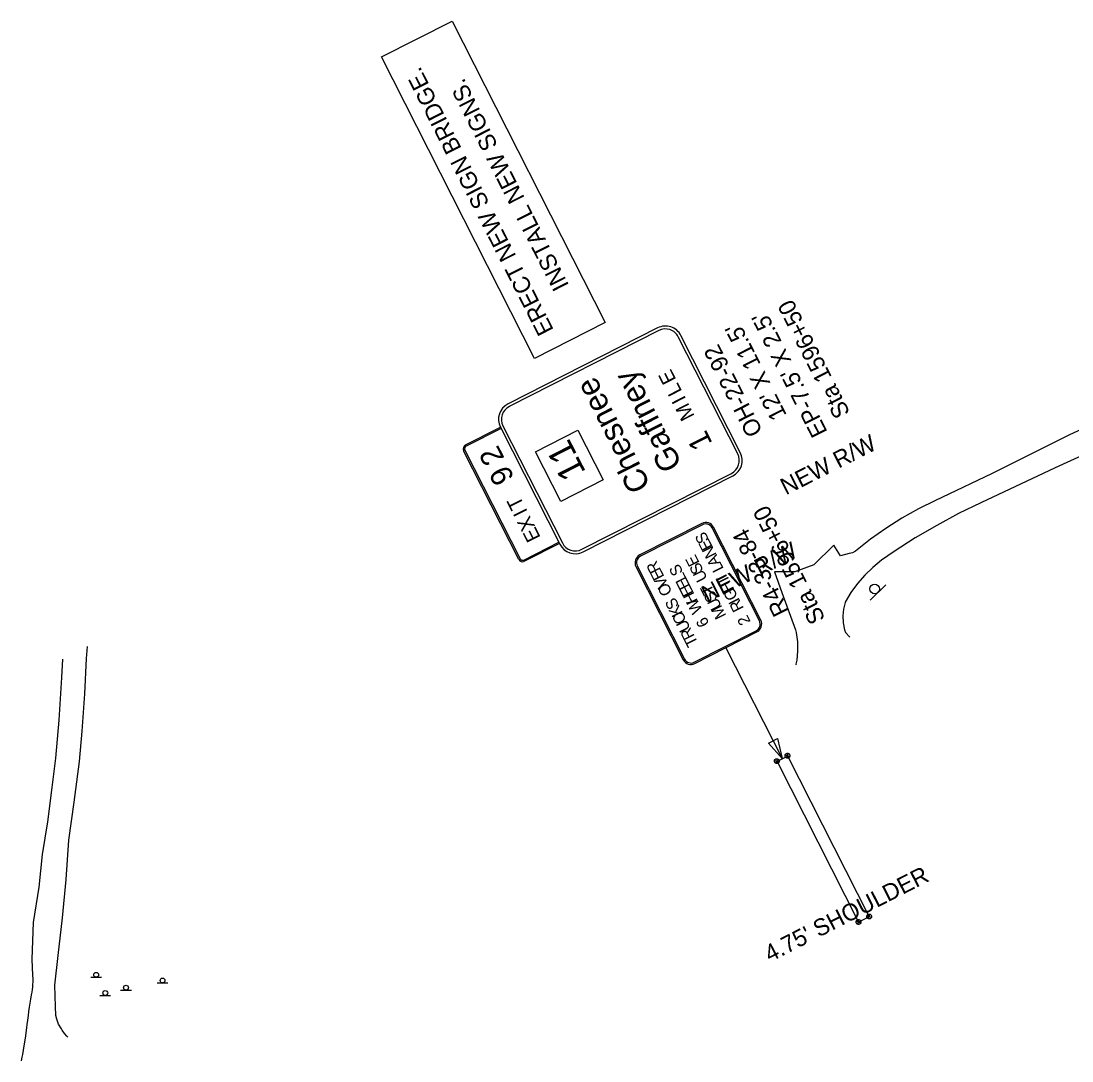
# Model space of a CAD drawing. Extents: x 1806030 to 1807588, y 1188872 to 1190302.
# Drawn here: x 1806373.9 to 1806808.9, y 1189423.6 to 1189854 of the extents above; entities that cross this region are included whole.
import ezdxf

# ---------------------------------------------------------------- set-up
doc = ezdxf.new("R2010")
doc.units = 0
for name, color, linetype in [('RD_EX_Road', 7, 'Continuous'), ('RD_PD_Final_TX', 7, 'Continuous'), ('RD_PD_RW_TX', 7, 'Continuous'), ('SN_P_Signs', 7, 'Continuous')]:
    doc.layers.add(name, color=color, linetype=linetype)

msp = doc.modelspace()

# ---------------------------------------------------------------- linework, layer by layer
at = {"layer": 'RD_EX_Road'}
for points in [[(1806841.36, 1189698.26), (1806807.68, 1189682.56), (1806775.95, 1189666.81), (1806755.12, 1189656.88), (1806752.39, 1189655.63), (1806745.38, 1189652.11), (1806738.55, 1189648.25), (1806731.93, 1189644.05), (1806725.53, 1189639.52), (1806719.36, 1189634.67), (1806718.02, 1189633.98), (1806716.66, 1189633.64), (1806713.08, 1189632.65), (1806710.3, 1189637.13), (1806702.13, 1189628.91), (1806694.17, 1189626.05), (1806685.79, 1189626), (1806688.83, 1189617.5), (1806694.53, 1189602.11), (1806694.77, 1189600.9), (1806695.26, 1189597.09), (1806695.35, 1189593.26), (1806695.04, 1189589.44), (1806694.61, 1189587.88), (1806694.72, 1189587.51)], [(1806832.14, 1189682.96), (1806802.05, 1189669.06), (1806771.24, 1189654.68), (1806762, 1189650.16), (1806752.93, 1189645.29), (1806744.06, 1189640.07), (1806735.4, 1189634.52), (1806730.02, 1189630.82), (1806726.46, 1189627.9), (1806723.16, 1189624.69), (1806720.15, 1189621.2), (1806717.45, 1189617.47), (1806715.08, 1189613.52), (1806715.02, 1189613.41), (1806714.38, 1189610.62), (1806714.13, 1189607.78), (1806714.27, 1189604.92), (1806714.8, 1189602.11), (1806715.16, 1189600.9), (1806716.93, 1189599.03)], [(1806393.31, 1189433.47), (1806392.88, 1189433.84), (1806391.85, 1189435), (1806390.97, 1189436.29), (1806390.6, 1189436.95), (1806389.45, 1189438.86), (1806388.65, 1189440.95), (1806388.32, 1189442.47), (1806388.09, 1189446.15), (1806387.87, 1189454.99), (1806389.31, 1189467.19), (1806390.99, 1189482.78), (1806392.5, 1189498.73), (1806393.69, 1189515), (1806395.82, 1189530.65), (1806398.14, 1189547.51), (1806399.23, 1189560.09), (1806400.26, 1189575.6), (1806401.04, 1189590.17), (1806401.38, 1189595.11)], [(1806390.99, 1189589.96), (1806390.57, 1189582.3), (1806389.55, 1189564.61), (1806388.18, 1189548.93), (1806386.64, 1189536.83), (1806384.83, 1189522.61), (1806382.57, 1189509.07), (1806381.25, 1189495.55), (1806378.83, 1189480.85), (1806378.35, 1189465.79), (1806378.66, 1189458.95), (1806378.77, 1189457.79), (1806378.81, 1189456.51), (1806378.69, 1189455.04), (1806378.61, 1189454.08), (1806378.48, 1189453.16), (1806378.3, 1189452.14), (1806378.06, 1189450.91), (1806377.76, 1189449.17), (1806377.19, 1189445.88), (1806376.94, 1189444.04), (1806376.76, 1189442.42), (1806376.51, 1189440.46), (1806376.34, 1189438.75), (1806376.09, 1189437.29), (1806375.57, 1189432.98), (1806375.03, 1189429.83), (1806374.7, 1189428), (1806374.42, 1189426.27), (1806374.22, 1189425.23), (1806373.87, 1189423.59)]]:
    msp.add_lwpolyline(points, dxfattribs=at)
at = {"layer": 'SN_P_Signs'}
for p, q in [((1806523.05, 1189839.18), (1806552.3, 1189854.04)), ((1806552.3, 1189854.04), (1806615.68, 1189729.26)), ((1806586.44, 1189714.41), (1806523.05, 1189839.18)), ((1806615.68, 1189729.26), (1806586.44, 1189714.41)), ((1806637.9, 1189725.94), (1806576.02, 1189694.51)), ((1806586.88, 1189675.77), (1806604.43, 1189684.69)), ((1806604.43, 1189684.69), (1806614.88, 1189664.12)), ((1806606.06, 1189635.38), (1806667.94, 1189666.82)), ((1806614.88, 1189664.12), (1806597.33, 1189655.2)), ((1806725.46, 1189614.36), (1806731.82, 1189620.72)), ((1806665.69, 1189594.63), (1806688.95, 1189548.84)), ((1806691.25, 1189549.78), (1806686.83, 1189547.53)), ((1806690.21, 1189550.28), (1806692.1, 1189549.66)), ((1806690.85, 1189549.02), (1806691.47, 1189550.91)), ((1806724.99, 1189483.36), (1806691.25, 1189549.78)), ((1806685.79, 1189548.03), (1806687.69, 1189547.41)), ((1806686.43, 1189546.77), (1806687.05, 1189548.67)), ((1806686.83, 1189547.53), (1806720.58, 1189481.11)), ((1806724.68, 1189482.41), (1806725.3, 1189484.3)), ((1806719.63, 1189481.42), (1806721.52, 1189480.8)), ((1806720.27, 1189480.16), (1806720.89, 1189482.06)), ((1806720.58, 1189481.11), (1806724.99, 1189483.36)), ((1806724.05, 1189483.67), (1806725.94, 1189483.05)), ((1806402.73, 1189458.27), (1806407.23, 1189458.27)), ((1806430.21, 1189455.89), (1806434.71, 1189455.89)), ((1806406.48, 1189450.72), (1806410.98, 1189450.72)), ((1806415.08, 1189452.91), (1806419.58, 1189452.91))]:
    msp.add_line(p, q, dxfattribs=at)
for points in [[(1806637.35, 1189727.01), (1806575.48, 1189695.58)], [(1806670.57, 1189674.88), (1806645.97, 1189723.31)], [(1806671.64, 1189675.43), (1806647.04, 1189723.85)], [(1806557.88, 1189678.56), (1806572.32, 1189685.9), (1806572.59, 1189685.36)], [(1806572.59, 1189685.36), (1806558.15, 1189678.03)], [(1806572.32, 1189685.9), (1806596.92, 1189637.47)], [(1806573.39, 1189686.44), (1806597.99, 1189638.01)], [(1806579.92, 1189631.21), (1806557.09, 1189676.14)], [(1806557.62, 1189676.41), (1806580.45, 1189631.48)], [(1806597.33, 1189655.2), (1806586.88, 1189675.77)], [(1806606.6, 1189634.31), (1806668.48, 1189665.75)], [(1806655.7, 1189646.08), (1806630.02, 1189633.04)], [(1806655.97, 1189645.55), (1806630.29, 1189632.5)], [(1806679.57, 1189605.72), (1806660, 1189644.23)], [(1806680.1, 1189605.99), (1806660.54, 1189644.5)], [(1806582.06, 1189630.95), (1806596.51, 1189638.29), (1806596.78, 1189637.75), (1806582.34, 1189630.42)], [(1806628.44, 1189628.2), (1806648.01, 1189589.68)], [(1806628.98, 1189628.47), (1806648.54, 1189589.96)], [(1806652.58, 1189588.64), (1806678.25, 1189601.68)], [(1806652.85, 1189588.1), (1806678.53, 1189601.15)], [(1806691.61, 1189549.07), (1806691.45, 1189549.01), (1806691.29, 1189548.97), (1806691.12, 1189548.97), (1806690.96, 1189548.98), (1806690.8, 1189549.03), (1806690.65, 1189549.1), (1806690.51, 1189549.2), (1806690.39, 1189549.32), (1806690.3, 1189549.45), (1806690.22, 1189549.6), (1806690.18, 1189549.76), (1806690.16, 1189549.93), (1806690.16, 1189550.1), (1806690.2, 1189550.26), (1806690.26, 1189550.42), (1806690.35, 1189550.56), (1806690.46, 1189550.68), (1806690.59, 1189550.79), (1806690.7, 1189550.86)], [(1806690.7, 1189550.86), (1806690.86, 1189550.92), (1806691.02, 1189550.96), (1806691.19, 1189550.97), (1806691.35, 1189550.95), (1806691.51, 1189550.9), (1806691.66, 1189550.83), (1806691.8, 1189550.73), (1806691.92, 1189550.61), (1806692.02, 1189550.48), (1806692.09, 1189550.33), (1806692.14, 1189550.17), (1806692.15, 1189550), (1806692.15, 1189549.83), (1806692.11, 1189549.67), (1806692.05, 1189549.52), (1806691.96, 1189549.37), (1806691.85, 1189549.25), (1806691.72, 1189549.14), (1806691.61, 1189549.07)], [(1806687.19, 1189546.83), (1806687.04, 1189546.77), (1806686.87, 1189546.73), (1806686.7, 1189546.72), (1806686.54, 1189546.74), (1806686.38, 1189546.79), (1806686.23, 1189546.86), (1806686.09, 1189546.96), (1806685.97, 1189547.07), (1806685.88, 1189547.21), (1806685.8, 1189547.36), (1806685.76, 1189547.52), (1806685.74, 1189547.69), (1806685.75, 1189547.85), (1806685.78, 1189548.02), (1806685.84, 1189548.17), (1806685.93, 1189548.31), (1806686.04, 1189548.44), (1806686.17, 1189548.54), (1806686.28, 1189548.61)], [(1806686.28, 1189548.61), (1806686.44, 1189548.68), (1806686.6, 1189548.71), (1806686.77, 1189548.72), (1806686.93, 1189548.7), (1806687.1, 1189548.65), (1806687.25, 1189548.58), (1806687.38, 1189548.49), (1806687.5, 1189548.37), (1806687.6, 1189548.23), (1806687.67, 1189548.08), (1806687.72, 1189547.92), (1806687.74, 1189547.76), (1806687.73, 1189547.59), (1806687.69, 1189547.43), (1806687.63, 1189547.27), (1806687.54, 1189547.13), (1806687.43, 1189547), (1806687.3, 1189546.9), (1806687.19, 1189546.83)], [(1806725.45, 1189482.47), (1806725.29, 1189482.4), (1806725.13, 1189482.37), (1806724.96, 1189482.36), (1806724.8, 1189482.38), (1806724.64, 1189482.42), (1806724.49, 1189482.5), (1806724.35, 1189482.59), (1806724.23, 1189482.71), (1806724.13, 1189482.85), (1806724.06, 1189483), (1806724.01, 1189483.16), (1806723.99, 1189483.32), (1806724, 1189483.49), (1806724.04, 1189483.65), (1806724.1, 1189483.81), (1806724.19, 1189483.95), (1806724.3, 1189484.07), (1806724.43, 1189484.18), (1806724.54, 1189484.25)], [(1806724.54, 1189484.25), (1806724.7, 1189484.31), (1806724.86, 1189484.35), (1806725.03, 1189484.36), (1806725.19, 1189484.34), (1806725.35, 1189484.29), (1806725.5, 1189484.22), (1806725.64, 1189484.12), (1806725.76, 1189484), (1806725.85, 1189483.87), (1806725.93, 1189483.72), (1806725.97, 1189483.56), (1806725.99, 1189483.39), (1806725.99, 1189483.23), (1806725.95, 1189483.06), (1806725.89, 1189482.91), (1806725.8, 1189482.77), (1806725.69, 1189482.64), (1806725.56, 1189482.53), (1806725.45, 1189482.47)], [(1806721.03, 1189480.22), (1806720.87, 1189480.16), (1806720.71, 1189480.12), (1806720.54, 1189480.11), (1806720.38, 1189480.13), (1806720.22, 1189480.18), (1806720.07, 1189480.25), (1806719.93, 1189480.35), (1806719.81, 1189480.47), (1806719.72, 1189480.6), (1806719.64, 1189480.75), (1806719.6, 1189480.91), (1806719.58, 1189481.08), (1806719.58, 1189481.24), (1806719.62, 1189481.41), (1806719.68, 1189481.56), (1806719.77, 1189481.7), (1806719.88, 1189481.83), (1806720.01, 1189481.94), (1806720.12, 1189482)], [(1806720.12, 1189482), (1806720.28, 1189482.07), (1806720.44, 1189482.1), (1806720.61, 1189482.11), (1806720.77, 1189482.09), (1806720.93, 1189482.05), (1806721.08, 1189481.97), (1806721.22, 1189481.88), (1806721.34, 1189481.76), (1806721.44, 1189481.62), (1806721.51, 1189481.47), (1806721.56, 1189481.31), (1806721.57, 1189481.15), (1806721.57, 1189480.98), (1806721.53, 1189480.82), (1806721.47, 1189480.66), (1806721.38, 1189480.52), (1806721.27, 1189480.4), (1806721.14, 1189480.29), (1806721.03, 1189480.22)]]:
    msp.add_lwpolyline(points, dxfattribs=at)
msp.add_lwpolyline([(1806686.97, 1189557.06), (1806688.95, 1189548.84), (1806683.33, 1189555.16)], close=True, dxfattribs=at)
for centre, radius in [((1806727.22, 1189618.99), 2), ((1806404.99, 1189459.28), 1), ((1806432.47, 1189456.91), 1), ((1806417.34, 1189453.92), 1), ((1806408.74, 1189451.73), 1)]:
    msp.add_circle(centre, radius, dxfattribs=at)
for centre, radius, start, end in [((1806640.62, 1189720.59), 7.2, 26.9317, 116.9317), ((1806640.62, 1189720.59), 6, 26.9317, 116.9317), ((1806578.74, 1189689.16), 7.2, 116.9317, 206.9317), ((1806578.74, 1189689.16), 6, 116.9317, 206.9317), ((1806558.69, 1189676.96), 1.8, 116.9317, 206.9317), ((1806558.69, 1189676.96), 1.2, 116.9317, 206.9317), ((1806665.22, 1189672.17), 7.2, 296.9317, 26.9317), ((1806665.22, 1189672.17), 6, 296.9317, 26.9317), ((1806657.33, 1189642.87), 3.6, 26.9317, 116.9317), ((1806657.33, 1189642.87), 3, 26.9317, 116.9317), ((1806603.34, 1189640.73), 7.2, 206.9317, 296.9317), ((1806603.34, 1189640.73), 6, 206.9317, 296.9317), ((1806631.65, 1189629.83), 3.6, 116.9317, 206.9317), ((1806631.65, 1189629.83), 3, 116.9317, 206.9317), ((1806581.52, 1189632.02), 1.8, 206.9317, 296.9317), ((1806581.52, 1189632.02), 1.2, 206.9317, 296.9317), ((1806676.89, 1189604.36), 3, 296.9317, 26.9317), ((1806676.89, 1189604.36), 3.6, 296.9317, 26.9317), ((1806651.22, 1189591.31), 3.6, 206.9317, 296.9317), ((1806651.22, 1189591.31), 3, 206.9317, 296.9317)]:
    msp.add_arc(centre, radius, start, end, dxfattribs=at)

# ---------------------------------------------------------------- texts
at = {"layer": 'RD_PD_Final_TX'}
msp.add_text("4.75' SHOULDER", height=7, rotation=27.034, dxfattribs=at).set_placement((1806683.9, 1189464.34))
at = {"layer": 'RD_PD_RW_TX'}
for p in [(1806690.52, 1189657.67), (1806657.88, 1189613.21)]:
    msp.add_text('NEW R/W', height=7, rotation=26.8778, dxfattribs=at).set_placement(p)
at = {"layer": 'SN_P_Signs'}
for s, height, p in [('ERECT NEW SIGN BRIDGE.', 6.9998, (1806594.56, 1189726.13)), ('INSTALL NEW SIGNS.', 6.9998, (1806600.88, 1189744.58)), ('Sta 1596+50', 7, (1806717.24, 1189691.8)), ("EP-7.5' X 2.5'", 7, (1806707.88, 1189683.96)), ("12' X 11.5'", 7, (1806691, 1189690.9)), ('OH-22-92', 7, (1806681.09, 1189684.14)), ('Chesnee', 9.6, (1806634.73, 1189661.74)), ('Gaffney', 9.6, (1806647.78, 1189670.42)), ('E', 6, (1806645.23, 1189705.56)), ('L', 6, (1806647.68, 1189700.72)), ('I', 6, (1806649.31, 1189697.52)), ('M', 6, (1806652.87, 1189690.5)), ('1', 9, (1806660.28, 1189679.24)), ('11', 10.8, (1806607.85, 1189667.3)), ('2', 9, (1806574.17, 1189672.99)), ('9', 9, (1806578.29, 1189664.88)), ('T', 6, (1806582.33, 1189653.61)), ('I', 6, (1806583.68, 1189650.95)), ('X', 6, (1806586.77, 1189644.88)), ('Sta 1596+50', 7, (1806707.01, 1189606.61)), ('E', 6, (1806589.1, 1189640.28)), ('S', 4.8, (1806658.84, 1189639.23)), ('R4-33-84', 7, (1806692.04, 1189609.82)), ('E', 4.8, (1806660.3, 1189636.36)), ('N', 4.8, (1806661.95, 1189633.12)), ('E', 4.8, (1806654.89, 1189629.78)), ('A', 4.8, (1806663.67, 1189629.72)), ('R', 4.8, (1806638.85, 1189626.92)), ('E', 4.8, (1806640.31, 1189624.05)), ('S', 4.8, (1806648.12, 1189625.9)), ('S', 4.8, (1806656.54, 1189626.54)), ('L', 4.8, (1806664.88, 1189627.34)), ('L', 4.8, (1806649.57, 1189623.04)), ('E', 4.8, (1806651.03, 1189620.17)), ('U', 4.8, (1806658.19, 1189623.3)), ('T', 4.8, (1806667.6, 1189621.99)), ('V', 4.8, (1806642, 1189620.72)), ('O', 4.8, (1806643.62, 1189617.53)), ('E', 4.8, (1806652.48, 1189617.31)), ('T', 4.8, (1806660.9, 1189617.95)), ('H', 4.8, (1806669.16, 1189618.93)), ('G', 4.8, (1806670.8, 1189615.69)), ('S', 4.8, (1806646.44, 1189611.98)), ('H', 4.8, (1806654.13, 1189614.07)), ('S', 4.8, (1806662.46, 1189614.89)), ('U', 4.8, (1806664.11, 1189611.65)), ('I', 4.8, (1806671.57, 1189614.19)), ('R', 4.8, (1806673.21, 1189610.94)), ('K', 4.8, (1806648, 1189608.91)), ('W', 4.8, (1806656.12, 1189610.14)), ('M', 4.8, (1806665.97, 1189607.97)), ('C', 4.8, (1806649.55, 1189605.85)), ('U', 4.8, (1806651.2, 1189602.61)), ('6', 4.8, (1806658.94, 1189604.59)), ('2', 4.8, (1806676.03, 1189605.39)), ('R', 4.8, (1806652.85, 1189599.37)), ('T', 4.8, (1806654.3, 1189596.51))]:
    msp.add_text(s, height=height, rotation=116.9317, dxfattribs=at).set_placement(p)

doc.saveas('drawing.dxf')
